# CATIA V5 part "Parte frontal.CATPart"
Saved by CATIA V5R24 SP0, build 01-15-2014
Part number: Parte frontal
Bounding box of the stored display mesh (mm): x 0 to 3, y -200 to 200, z -225 to 225
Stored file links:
  C:\Users\Fatec\Desktop\Maquina componentes catia\Parte frontal.CATPart
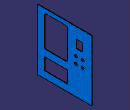
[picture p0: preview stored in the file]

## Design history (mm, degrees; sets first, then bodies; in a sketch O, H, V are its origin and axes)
Body1 (main body)
  Sketch1 on yz-plane, origin (0, 0, 0), H (0, 1, 0), V (0, 0, 1)
    line L1 (-200, 225) -> (200, 225)
    line L2 (200, 225) -> (200, -225)
    line L3 (200, -225) -> (-200, -225)
    line L4 (-200, -225) -> (-200, 225)
    length L3 = 400
    length L4 = 450
    horizontal: L1 H, L3 H
    vertical: L2 V, L4 V
    symmetry: L4 L2 V, L3 L1 H
  Pad1: profile Sketch1, direction (1, 0, 0), length 3
  Sketch2 on end face of Pad1, origin (3, 0, 0), H (0, 1, 0), V (0, 0, 1)
    reference projected line E1 (-200, 225) -> (-200, -225) from edge [face of Pad1 from Sketch1.L4 | end face of Pad1]
    reference projected line E2 (-200, -225) -> (200, -225) from edge [face of Pad1 from Sketch1.L3 | end face of Pad1]
    reference projected line E3 (200, -225) -> (200, 225) from edge [face of Pad1 from Sketch1.L2 | end face of Pad1]
    reference projected line E4 (200, 225) -> (-200, 225) from edge [face of Pad1 from Sketch1.L1 | end face of Pad1]
    line L1 (-150, -85) -> (20, -85)
    line L2 (20, -85) -> (20, -175)
    line L3 (20, -175) -> (-150, -175)
    line L4 (-150, -175) -> (-150, -85)
    point P13 (-150, 195)
    line L5 (-137, 195) -> (7, 195)
    line L6 (20, 182) -> (20, -22)
    line L7 (7, -35) -> (-137, -35)
    line L8 (-150, -22) -> (-150, 182)
    point P14 (20, -35)
    point P15 (-150, -35)
    line L9 (85, 145) -> (130, 145)
    line L10 (130, 145) -> (130, 85)
    line L11 (130, 85) -> (85, 85)
    line L12 (85, 85) -> (85, 145)
    circle A1 centre (82.5, 35) radius 10.5
    point P20 (82.5, 35)
    circle A2 centre (132.5, 35) radius 10.5
    point P21 (132.5, 35)
    point P22 (77.4246, -37.4246)
    circle A3 centre (132.5, -15) radius 10.5
    point P23 (132.5, -15)
    arc A4 centre (7, 182) radius 13 from (7, 195) to (20, 182) cw
    arc A5 centre (-137, 182) radius 13 from (-137, 195) to (-150, 182) ccw
    arc A6 centre (-137, -22) radius 13 from (-137, -35) to (-150, -22) cw
    arc A7 centre (7, -22) radius 13 from (20, -22) to (7, -35) cw
    circle A8 centre (82.5, -15) radius 10.5
    point P36 (82.5, -15)
    radius A3 = 10.5
    radius A2 = 10.5
    radius A1 = 10.5
    distance L3 E2 = 50
    distance L5 E4 = 30
    length L4 = 90
    length L3 = 170
    distance L4 E1 = 50
    distance L8 E1 = 50
    radius A4 = 13
    distance P15 P13 = 230
    radius A5 = 13
    distance P14 P15 = 170
    radius A6 = 13
    radius A7 = 13
    length L11 = 45
    length L10 = 60
    distance L10 E3 = 70
    distance L9 E4 = 80
    distance P20 L11 = 50
    distance P20 P21 = 50
    distance P21 E3 = 67.5
    distance P23 E3 = 67.5
    distance P23 P21 = 50
    radius A8 = 10.5
    distance P36 P23 = 50
    distance P36 P20 = 50
    distance P21 L11 = 50
    horizontal: L1 H, L3 H, L5 H, L7 H, L9 H, L11 H
    vertical: L2 V, L4 V, L6 V, L8 V, L10 V, L12 V
    tangency: A4 L5, A4 L6, A5 L5, A5 L8, A6 L7, A6 L8, A7 L6, A7 L7
    coincidence: L5 P13, L8 P13, L7 P15, L8 P15, L6 P14, L7 P14
  Pocket1: profile Sketch2, direction (-1, 0, 0), through (limit type 6)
